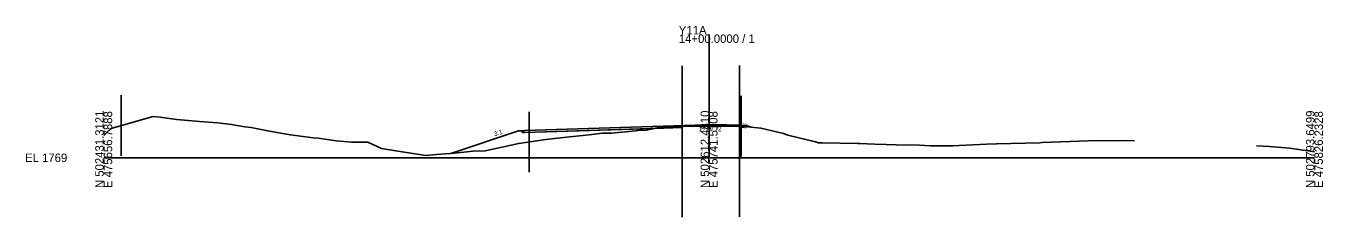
# Model space of a CAD drawing. Extents: x -26 to 403, y -10 to 5098.
# Drawn here: x -25.7 to 402.8, y 3980.4 to 4043.6 of the extents above; entities that cross this region are included whole.
import ezdxf

# ---------------------------------------------------------------- set-up
doc = ezdxf.new("R2010")
doc.units = 0
for name, color, linetype in [('Exist Cross Section Cell', 7, 'Continuous'), ('Exist XS Center Line Elevation Label', 7, 'Continuous'), ('Exist XS Ground Line', 7, 'Continuous'), ('Prop XS Dump Level', 7, 'Continuous'), ('Prop XS Earthwork Shape', 7, 'Continuous'), ('Prop XS Finish Grade', 7, 'Continuous'), ('Prop XS Finish Grade Earthwork', 7, 'Continuous'), ('Prop XS Finish Grade Pavement', 7, 'Continuous'), ('Prop XS Pvmt Edge Slope', 7, 'Continuous'), ('Prop XS Shoulder Borrow Shape', 7, 'Continuous'), ('Prop XS Side Slope Text', 7, 'Continuous'), ('Prop XS Subgrade Earthwork', 7, 'Continuous'), ('Scratch_Level_1', 7, 'Continuous'), ('Scratch_Level_5', 7, 'Continuous'), ('Scratch_Level_6', 7, 'Continuous')]:
    doc.layers.add(name, color=color, linetype=linetype)

msp = doc.modelspace()

# ---------------------------------------------------------------- linework, layer by layer
at = {"layer": 'Exist Cross Section Cell'}
for p, q in [((200, 4000), (200, 4040.76)), ((0, 4000), (200, 4000)), ((200, 4000), (400, 4000))]:
    msp.add_line(p, q, dxfattribs=at)
at = {"layer": 'Exist XS Ground Line'}
for points in [[(0, 4007.34), (1.02, 4008.39), (2.4, 4009.54), (2.75, 4009.84), (16.37, 4013.59), (18.63, 4013.44), (24.09, 4012.6), (26.65, 4012.41), (31.62, 4011.98), (37.69, 4011.57), (42.24, 4011), (46.66, 4010.24), (48.73, 4009.96), (54.19, 4008.89), (59.77, 4007.92), (61.71, 4007.58), (65.85, 4007.05), (69.23, 4006.6), (70.81, 4006.47), (76.76, 4005.57), (81.86, 4005.13), (86.89, 4005.18), (87.28, 4005.14), (91.8, 4003.12), (96.56, 4002.32), (106.39, 4000.74), (109.89, 4001.04), (115.84, 4001.48), (121.9, 4002.16), (126.02, 4002.35), (137.1, 4004.73), (146.02, 4006), (151.94, 4006.69), (160.33, 4007.59), (164.65, 4008.17), (165, 4008.09), (165.85, 4008.11), (167.92, 4008.18), (175.73, 4008.94), (176.11, 4008.97), (176.44, 4008.98), (179.23, 4009.1), (182.86, 4009.9), (190.36, 4010.32), (190.97, 4010.34), (191.39, 4010.38), (192.1, 4010.47), (194.09, 4010.53), (194.69, 4010.56), (195.48, 4010.58), (197.53, 4010.64), (199.59, 4010.71), (200.08, 4010.71), (200.58, 4010.73), (201.37, 4010.73), (202.97, 4010.71), (204.38, 4010.68), (205.72, 4010.65), (206.21, 4010.64), (207.26, 4010.61), (208.47, 4010.58), (209.28, 4010.55), (210, 4010.49), (210.6, 4010.43), (214.85, 4010.03), (217.14, 4009.81), (224.61, 4007.98), (226.01, 4007.49), (235.13, 4005.22), (236.11, 4004.99), (236.5, 4004.97), (237.42, 4004.96), (249, 4004.71), (249.79, 4004.72), (254.74, 4004.5), (258.52, 4004.35), (261.84, 4004.3), (269.56, 4004.17), (273.06, 4003.93), (278.35, 4003.98), (280.6, 4003.94), (282.58, 4004.05), (291.64, 4004.48), (294.93, 4004.66), (309.28, 4004.97), (310.06, 4005.01), (325.27, 4005.55), (337.21, 4005.74), (340.59, 4005.6)], [(380.83, 4003.98), (385.16, 4003.7), (391.71, 4003.17), (398.55, 4002.15), (400, 4002.02)]]:
    msp.add_lwpolyline(points, dxfattribs=at)
at = {"layer": 'Prop XS Earthwork Shape'}
for points in [[(139.06, 4008.36), (181.96, 4009.7), (179.23, 4009.1), (176.44, 4008.98), (176.11, 4008.97), (175.73, 4008.94), (167.92, 4008.18), (165.85, 4008.11), (165, 4008.09), (164.65, 4008.17), (160.33, 4007.59), (151.94, 4006.69), (146.02, 4006), (137.1, 4004.73), (126.02, 4002.35), (121.9, 4002.16), (115.84, 4001.48), (114.65, 4001.39), (137.06, 4008.86), (137.8, 4008.92), (138.38, 4008.34)], [(181.96, 4009.7), (182.86, 4009.9), (190.36, 4010.32), (190.97, 4010.34), (191.11, 4010.35), (191.11, 4009.99)], [(210.05, 4010.08), (211.28, 4010.05), (211.57, 4010.34), (210.6, 4010.43), (210.05, 4010.49)], [(211.57, 4010.34), (211.86, 4010.63), (212.59, 4010.57), (213.94, 4010.12)]]:
    msp.add_lwpolyline(points, close=True, dxfattribs=at)
at = {"layer": 'Prop XS Finish Grade'}
for p, q in [((139.06, 4009.02), (137.8, 4008.92)), ((210.6, 4010.73), (211.86, 4010.63))]:
    msp.add_line(p, q, dxfattribs=at)
at = {"layer": 'Prop XS Finish Grade Earthwork'}
for p, q in [((137.06, 4008.86), (114.65, 4001.39)), ((137.8, 4008.92), (137.06, 4008.86)), ((211.86, 4010.63), (212.59, 4010.57)), ((212.59, 4010.57), (213.94, 4010.12))]:
    msp.add_line(p, q, dxfattribs=at)
at = {"layer": 'Prop XS Finish Grade Pavement'}
msp.add_lwpolyline([(139.06, 4009.02), (195.44, 4010.79), (197.44, 4010.85), (199.14, 4010.9), (200, 4010.93), (200.35, 4010.94), (201.34, 4010.94), (202.98, 4010.92), (204.43, 4010.89), (205.74, 4010.86), (210.6, 4010.73)], dxfattribs=at)
at = {"layer": 'Prop XS Pvmt Edge Slope'}
for p, q in [((139.06, 4009.02), (138.38, 4008.34)), ((210.6, 4010.73), (211.28, 4010.05))]:
    msp.add_line(p, q, dxfattribs=at)
at = {"layer": 'Prop XS Shoulder Borrow Shape'}
for points in [[(139.06, 4009.02), (137.8, 4008.92), (138.38, 4008.34)], [(210.6, 4010.73), (211.28, 4010.05), (211.86, 4010.63)]]:
    msp.add_lwpolyline(points, close=True, dxfattribs=at)
at = {"layer": 'Prop XS Subgrade Earthwork'}
for p, q in [((138.38, 4008.34), (137.8, 4008.92)), ((139.06, 4008.36), (138.38, 4008.34)), ((191.11, 4010.35), (191.11, 4009.99)), ((210.05, 4010.49), (210.05, 4010.08)), ((210.05, 4010.08), (211.29, 4010.05)), ((211.28, 4010.05), (211.86, 4010.63))]:
    msp.add_line(p, q, dxfattribs=at)
msp.add_lwpolyline([(139.06, 4008.36), (191.11, 4009.99)], dxfattribs=at)
at = {"layer": 'Scratch_Level_1'}
for p, q in [((191.11, 4030.41), (191.11, 3980.41)), ((210.05, 4030.52), (210.05, 3980.52))]:
    msp.add_line(p, q, dxfattribs=at)
at = {"layer": 'Scratch_Level_5'}
for p, q in [((5.72, 4020.66), (5.72, 4000.66)), ((210.6, 4020.43), (210.6, 4000.43)), ((140.58, 4015.22), (140.58, 3995.22))]:
    msp.add_line(p, q, dxfattribs=at)
at = {"layer": 'Scratch_Level_6'}
msp.add_line((191.11, 4010.35), (210.05, 4010.49), dxfattribs=at)

# ---------------------------------------------------------------- texts
at = {"layer": 'Exist Cross Section Cell'}
for s, p in [('Y11A', (190, 4040.76)), ('14+00.0000 / 1', (190, 4037.96)), ('EL 1769', (-26, 3998.6))]:
    msp.add_text(s, height=2.8, dxfattribs=at).set_placement(p)
for s, p in [('N 502431.3121', (0, 3990)), ('N 502612.4810', (200, 3990)), ('N 502793.6499', (400, 3990)), ('E 475656.7888', (2.8, 3990)), ('E 475741.5108', (202.8, 3990)), ('E 475826.2328', (402.8, 3990))]:
    msp.add_text(s, height=2.8, rotation=90, dxfattribs=at).set_placement(p)
at = {"layer": 'Exist XS Center Line Elevation Label'}
msp.add_text('1779.72', height=1.5, dxfattribs=at).set_placement((196.63, 4008.77))
at = {"layer": 'Prop XS Dump Level'}
for p in [(134.06, 4008.58), (213.14, 4010.51)]:
    msp.add_text('Case1', height=0.04, dxfattribs=at).set_placement(p)
at = {"layer": 'Prop XS Side Slope Text'}
for rotation, p in [(162.2458, (212.83, 4011.05)), (18.4349, (129.16, 4007.06))]:
    msp.add_text('3:1', height=1.5, rotation=rotation, dxfattribs=at).set_placement(p)

doc.saveas('drawing.dxf')
